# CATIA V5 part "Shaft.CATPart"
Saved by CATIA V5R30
Part number: Shaft
Bounding box of the stored display mesh (mm): x -10.997 to 10.997, y 0 to 134, z -10.875 to 10.875
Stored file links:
  D:\PROJECTS\CATIA V56R 2020\Resources\Parts File\c14_catia_v5_6r2020_prt\c14-catia-v5-6r2020-figr-14-26 & 27\Part & Asm\Shaft.CATPart
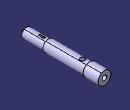
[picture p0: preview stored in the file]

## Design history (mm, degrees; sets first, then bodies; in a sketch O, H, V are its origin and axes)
Body1 (main body)
  Sketch1 on yz-plane, origin (0, 0, 0), H (0, 1, 0), V (0, 0, 1)
    line L1 (0, 0) -> (0, 8)
    line L2 (0, 8) -> (39, 8)
    line L3 (39, 8) -> (39, 9.5)
    line L4 (39, 9.5) -> (109, 9.5)
    line L5 (109, 9.5) -> (109, 11)
    line L6 (109, 11) -> (134, 11)
    line L7 (134, 11) -> (134, 0)
    point P7 (134, 0)
    line L8 (134, 0) -> (0, 0)
    length L1 = 8
    length L8 = 134
    length L7 = 11
    distance L4 L8 = 9.5
    length L6 = 25
    length L4 = 70
    vertical: L1 V, L3 V, L5 V, L7 V
    horizontal: L2 H, L4 H, L6 H, L8 H
    coincidence: P7 H
  Shaft1: profile Sketch1, axis edge of Sketch1, angle 360
  Chamfer1: length 1.5, angle 45, on 1 edge
  Sketch2 on xy-plane, origin (0, 0, 0), H (1, 0, 0), V (0, 1, 0)
    circle A1 centre (0, 97) radius 4.15
    point P1 (0, 97)
    reference projected line E1 (-11, 109) -> (11, 109) from edge of Shaft1
    radius A1 = 4.15
    distance E1 P1 = 12
    coincidence: P1 V
  Pocket1: profile Sketch2, direction (0, 0, -1), length 20, mirrored extent
  Sketch3 on face of Shaft1, origin (0, 134, 0), H (-1, 0, 0), V (0, 0, 1)
    circle A1 centre (0, 0) radius 4.15
    radius A1 = 4.15
  Pocket2: profile Sketch3, direction (0, -1, 0), length 44
  Sketch4 on yz-plane, origin (0, 0, 0), H (0, 1, 0), V (0, 0, 1)
    point P1 (23, 8)
    line L1 (23, 8) -> (33, 8)
    arc A1 centre (28, 12.899) radius 7 from (23, 8) to (33, 8) ccw
    reference projected line E1 (39, -9.5) -> (39, 9.5) from edge of Shaft1
    length L1 = 10
    distance L1 H = 8
    distance P1 E1 = 16
    radius A1 = 7
    horizontal: L1 H
  Pocket3: profile Sketch4, direction (-1, 0, 0), length 1.6, mirrored extent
